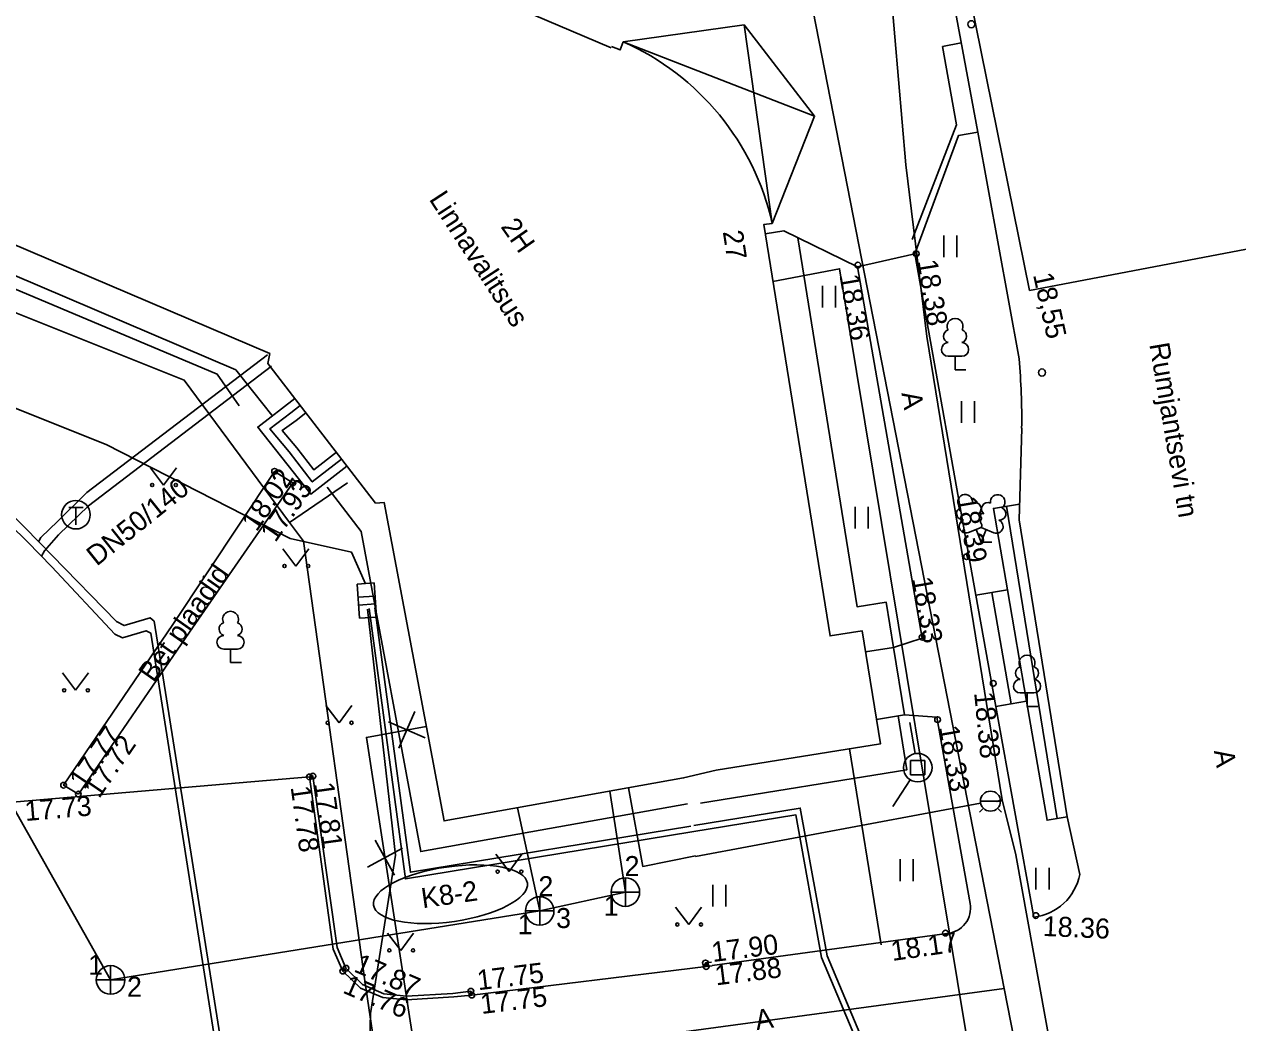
# Model space of a CAD drawing. Extents: x 713497 to 713863, y 6590062 to 6590327.
# Drawn here: x 713604.95 to 713647.37, y 6590159.98 to 6590194.89 of the extents above; entities that cross this region are included whole.
import ezdxf

# ---------------------------------------------------------------- set-up
doc = ezdxf.new("R2010")
doc.units = 0
for name, color, linetype in [('AED', 7, 'Continuous'), ('DKAEV', 7, 'Continuous'), ('HALJASTUS', 7, 'Continuous'), ('HOONE', 7, 'Continuous'), ('HOONEDET', 7, 'Continuous'), ('KAEVU_NR', 7, 'Continuous'), ('KKAEV', 7, 'Continuous'), ('KORGUS', 7, 'Continuous'), ('KTRASS', 7, 'Continuous'), ('MPKAABEL', 7, 'Continuous'), ('POST', 7, 'Continuous'), ('PUU', 7, 'Continuous'), ('SITRASS', 7, 'Continuous'), ('TEE', 7, 'Continuous'), ('TKAEV', 7, 'Continuous'), ('TORU NR', 7, 'Continuous'), ('TTRASS', 7, 'Continuous'), ('VKAEV', 7, 'Continuous'), ('VTRASS', 7, 'Continuous'), ('Слой 1', 7, 'Continuous')]:
    doc.layers.add(name, color=color, linetype=linetype)

msp = doc.modelspace()

# ---------------------------------------------------------------- linework, layer by layer
at = {"layer": 'AED'}
msp.add_lwpolyline([(713634.907, 6590162.705), (713633.803, 6590169.554)], dxfattribs=at)
at = {"layer": 'DKAEV'}
for p, q in [((713635.937, 6590168.645), (713635.937, 6590169.145)), ((713635.937, 6590169.145), (713636.437, 6590169.145)), ((713636.437, 6590169.145), (713636.437, 6590168.645)), ((713636.437, 6590168.645), (713635.937, 6590168.645))]:
    msp.add_line(p, q, dxfattribs=at)
msp.add_circle((713636.187, 6590168.895), 0.5, dxfattribs=at)
at = {"layer": 'HALJASTUS'}
for p, q in [((713637.102, 6590187.505), (713637.102, 6590186.744)), ((713637.558, 6590187.505), (713637.558, 6590186.744)), ((713632.856, 6590185.741), (713632.856, 6590184.98)), ((713633.311, 6590185.741), (713633.311, 6590184.98)), ((713637.718, 6590181.712), (713637.718, 6590180.951)), ((713638.173, 6590181.712), (713638.173, 6590180.951)), ((713609.359, 6590179.383), (713609.823, 6590178.776)), ((713609.823, 6590178.776), (713610.268, 6590179.383)), ((713633.997, 6590178.013), (713633.997, 6590177.252)), ((713634.453, 6590178.013), (713634.453, 6590177.252)), ((713613.986, 6590176.551), (713614.449, 6590175.944)), ((713614.449, 6590175.944), (713614.895, 6590176.551)), ((713606.283, 6590172.207), (713606.747, 6590171.6)), ((713606.747, 6590171.6), (713607.192, 6590172.207)), ((713615.499, 6590171.071), (713615.962, 6590170.464)), ((713615.962, 6590170.464), (713616.408, 6590171.071)), ((713621.437, 6590165.866), (713621.901, 6590165.259)), ((713621.901, 6590165.259), (713622.346, 6590165.866)), ((713635.571, 6590165.691), (713635.571, 6590164.93)), ((713636.026, 6590165.691), (713636.026, 6590164.93)), ((713640.321, 6590165.392), (713640.321, 6590164.631)), ((713640.776, 6590165.392), (713640.776, 6590164.631)), ((713629.028, 6590164.801), (713629.028, 6590164.04)), ((713629.483, 6590164.801), (713629.483, 6590164.04)), ((713627.72, 6590164.016), (713628.183, 6590163.41)), ((713628.183, 6590163.41), (713628.629, 6590164.016)), ((713617.65, 6590163.113), (713618.114, 6590162.506)), ((713618.114, 6590162.506), (713618.559, 6590163.113))]:
    msp.add_line(p, q, dxfattribs=at)
msp.add_lwpolyline([(713634.083, 6590186.407), (713636.085, 6590186.861)], dxfattribs=at)
for centre in [(713609.422, 6590178.776), (713610.251, 6590178.776), (713614.048, 6590175.944), (713614.877, 6590175.944), (713606.346, 6590171.6), (713607.174, 6590171.6), (713615.561, 6590170.464), (713616.39, 6590170.464), (713621.5, 6590165.259), (713622.328, 6590165.259), (713627.782, 6590163.41), (713628.611, 6590163.41), (713617.713, 6590162.506), (713618.541, 6590162.506)]:
    msp.add_circle(centre, 0.055, dxfattribs=at)
at = {"layer": 'HOONE'}
for points in [[(713591.105, 6590192.933), (713597.112, 6590207.263), (713600.77, 6590205.702), (713600.388, 6590204.728), (713625.464, 6590194.063)], [(713625.893, 6590194.273), (713630.115, 6590194.87), (713632.579, 6590191.676), (713631.097, 6590187.925)], [(713631.097, 6590187.925), (713630.801, 6590187.883), (713633.12, 6590173.501), (713634.243, 6590173.682), (713634.881, 6590169.727), (713629.138, 6590168.802), (713628.003, 6590168.533), (713619.626, 6590167.035), (713617.534, 6590178.165), (713617.232, 6590178.145), (713613.469, 6590183.026), (713613.531, 6590183.375), (713591.105, 6590192.933)], [(713616.233, 6590179.441), (713614.964, 6590178.463), (713613.113, 6590180.801), (713614.412, 6590181.803)], [(713634.362, 6590172.944), (713635.342, 6590173.102), (713635.722, 6590170.742), (713634.743, 6590170.584)], [(713636.1, 6590169.387), (713635.909, 6590170.468)], [(713635.917, 6590168.474), (713635.311, 6590167.533)]]:
    msp.add_lwpolyline(points, dxfattribs=at)
msp.add_arc((713622.223, 6590185.958), 9.09, 12.4976, 66.1826, dxfattribs=at)
at = {"layer": 'HOONEDET'}
for p, q in [((713631.097, 6590187.925), (713630.115, 6590194.87)), ((713632.579, 6590191.676), (713625.893, 6590194.273))]:
    msp.add_line(p, q, dxfattribs=at)
for points in [[(713596.129, 6590207.599), (713589.787, 6590192.438), (713612.343, 6590182.807), (713613.607, 6590181.216)], [(713625.478, 6590194.115), (713625.783, 6590193.994), (713625.893, 6590194.273)], [(713631.097, 6590187.925), (713630.801, 6590187.883), (713633.12, 6590173.501), (713634.243, 6590173.682), (713634.881, 6590169.727), (713629.138, 6590168.802)], [(713616.047, 6590179.682), (713615.016, 6590178.887), (713614.208, 6590179.934), (713613.54, 6590180.746), (713614.273, 6590181.306), (713614.6, 6590181.558)], [(713614.798, 6590181.303), (713614.453, 6590181.037), (713613.97, 6590180.689), (713614.483, 6590180.076), (713615.071, 6590179.314), (713615.861, 6590179.923)], [(713615.541, 6590178.701), (713616.733, 6590177.153), (713618.814, 6590165.958), (713628.14, 6590167.631)]]:
    msp.add_lwpolyline(points, dxfattribs=at)
msp.add_arc((713622.223, 6590185.958), 9.09, 12.4976, 66.1826, dxfattribs=at)
at = {"layer": 'KAEVU_NR'}
msp.add_ellipse((713619.851, 6590164.47), major_axis=(2.689, 0.388), ratio=0.353371, dxfattribs=at)
at = {"layer": 'KKAEV'}
for p, q in [((713625.965, 6590164.044), (713625.965, 6590165.044)), ((713625.465, 6590164.544), (713626.465, 6590164.544)), ((713622.97, 6590163.383), (713622.97, 6590164.383)), ((713622.47, 6590163.883), (713623.47, 6590163.883)), ((713607.97, 6590160.971), (713607.97, 6590161.971)), ((713607.47, 6590161.471), (713608.47, 6590161.471))]:
    msp.add_line(p, q, dxfattribs=at)
for centre in [(713625.965, 6590164.544), (713622.97, 6590163.883), (713607.97, 6590161.471)]:
    msp.add_circle(centre, 0.5, dxfattribs=at)
at = {"layer": 'KORGUS'}
for centre, radius in [((713638.06, 6590194.89), 0.125), ((713636.132, 6590186.867), 0.1), ((713634.096, 6590186.469), 0.1), ((713640.53, 6590182.71), 0.125), ((713613.702, 6590179.256), 0.1), ((713614.341, 6590178.855), 0.1), ((713637.893, 6590176.272), 0.1), ((713636.338, 6590173.454), 0.1), ((713638.828, 6590171.843), 0.1), ((713636.882, 6590170.572), 0.1), ((713606.327, 6590168.281), 0.1), ((713614.919, 6590168.57), 0.1), ((713615.041, 6590168.601), 0.1), ((713606.842, 6590167.969), 0.1), ((713640.319, 6590163.721), 0.1), ((713637.157, 6590163.111), 0.1), ((713616.198, 6590161.88), 0.1), ((713628.763, 6590162.064), 0.1), ((713628.791, 6590161.942), 0.1), ((713616.087, 6590161.78), 0.1), ((713620.564, 6590161.078), 0.1), ((713620.595, 6590160.942), 0.1)]:
    msp.add_circle(centre, radius, dxfattribs=at)
at = {"layer": 'KTRASS'}
for points in [[(713607.97, 6590161.471), (713597.64, 6590179.782)], [(713625.965, 6590164.544), (713625.424, 6590168.071)], [(713622.97, 6590163.883), (713622.198, 6590167.495)], [(713625.965, 6590164.544), (713622.97, 6590163.883)], [(713622.97, 6590163.883), (713607.97, 6590161.471)]]:
    msp.add_lwpolyline(points, dxfattribs=at)
at = {"layer": 'MPKAABEL'}
for points in [[(713649.332, 6590187.338), (713640.094, 6590185.585), (713635.77, 6590206.95), (713632.04, 6590224.25), (713630.57, 6590226.81), (713628.65, 6590228.67), (713627.42, 6590229.49), (713598.73, 6590243.21), (713583.058, 6590248.245), (713565.046, 6590256.189), (713523.612, 6590274.149), (713521.905, 6590274.877)], [(713616.886, 6590175.327), (713616.393, 6590176.426), (713614.251, 6590176.909), (713607.81, 6590180.2), (713588.598, 6590187.876), (713587.389, 6590189.739), (713589.126, 6590193.776), (713594.035, 6590205.549), (713591.42, 6590211.04), (713578.93, 6590215.939), (713578.375, 6590215.066)], [(713593.578, 6590189.232), (713594.274, 6590188.953), (713610.545, 6590182.449), (713614.229, 6590177.468)], [(713616.25, 6590178.85), (713614.229, 6590177.468)], [(713614.229, 6590177.468), (713614.715, 6590176.812), (713616.87, 6590161.36), (713618.55, 6590150.08)], [(713623.164, 6590135.391), (713619.07, 6590137.22), (713617.908, 6590148.88), (713616.96, 6590156.73), (713617.053, 6590160.295), (713617.928, 6590165.834), (713616.95, 6590174.44)], [(713628.288, 6590166.652), (713618.278, 6590165.005), (713617.01, 6590174.458)], [(713628.258, 6590166.852), (713618.45, 6590165.24), (713617.209, 6590174.485)], [(713628.364, 6590166.869), (713632.08, 6590167.48), (713633.015, 6590162.313), (713634.41, 6590159.02), (713637.59, 6590156.404), (713640.542, 6590143.998), (713655.527, 6590146.824), (713666.053, 6590148.923), (713666.104, 6590148.937), (713666.053, 6590148.923), (713676.52, 6590152.11), (713677.82, 6590153.38), (713679.31, 6590155.11), (713679.81, 6590159.44), (713679.75, 6590161.04), (713679.53, 6590162.08), (713679.1, 6590163.05), (713677.79, 6590165.07), (713675.3, 6590167.39), (713673.09, 6590169.87), (713671.63, 6590170.7), (713670.72, 6590170.92), (713670.037, 6590170.92)], [(713712.95, 6590130.05), (713709.16, 6590129.42), (713701.69, 6590129.47), (713690.5, 6590129.51), (713688.19, 6590129.12), (713683.66, 6590141.1), (713679.81, 6590148.4), (713679.37, 6590149.39), (713679.04, 6590150.26), (713678.83, 6590150.79), (713678.48, 6590151.44), (713677.98, 6590152.02), (713677.43, 6590152.31), (713676.95, 6590152.28), (713676.524, 6590152.014), (713670.183, 6590149.934), (713666.077, 6590148.723), (713655.565, 6590146.628), (713640.392, 6590143.766), (713637.411, 6590156.292), (713634.246, 6590158.892), (713632.822, 6590162.256), (713631.92, 6590167.25), (713628.288, 6590166.652)]]:
    msp.add_lwpolyline(points, dxfattribs=at)
at = {"layer": 'POST'}
for p, q in [((713617.18, 6590175.354), (713616.584, 6590175.314)), ((713616.584, 6590175.314), (713616.665, 6590174.122)), ((713617.261, 6590174.162), (713617.18, 6590175.354)), ((713617.211, 6590174.894), (713616.616, 6590174.853)), ((713617.229, 6590174.623), (713616.634, 6590174.582)), ((713616.665, 6590174.122), (713617.261, 6590174.162))]:
    msp.add_line(p, q, dxfattribs=at)
at = {"layer": 'PUU'}
for p, q in [((713637.732, 6590183.281), (713637.252, 6590183.281)), ((713637.492, 6590182.806), (713637.492, 6590183.281)), ((713637.872, 6590182.806), (713637.492, 6590182.806)), ((713637.96, 6590177.115), (713638.405, 6590177.29)), ((713638.4, 6590176.78), (713638.225, 6590177.22)), ((713638.4, 6590176.78), (713638.58, 6590177.22)), ((713638.405, 6590177.29), (713638.845, 6590177.11)), ((713638.78, 6590176.78), (713638.4, 6590176.78)), ((713612.403, 6590173.041), (713611.923, 6590173.041)), ((713612.163, 6590172.566), (713612.163, 6590173.041)), ((713612.543, 6590172.566), (713612.163, 6590172.566)), ((713640.248, 6590171.507), (713639.768, 6590171.507)), ((713640.008, 6590171.032), (713640.008, 6590171.507)), ((713640.388, 6590171.032), (713640.008, 6590171.032))]:
    msp.add_line(p, q, dxfattribs=at)
msp.add_lwpolyline([(713638.405, 6590177.785), (713638.385, 6590177.71), (713638.385, 6590177.69), (713638.395, 6590177.66), (713638.415, 6590177.625), (713638.42, 6590177.605), (713638.405, 6590177.57), (713638.38, 6590177.52), (713638.375, 6590177.495), (713638.38, 6590177.48), (713638.39, 6590177.45), (713638.425, 6590177.39), (713638.43, 6590177.37), (713638.425, 6590177.35), (713638.41, 6590177.315), (713638.405, 6590177.29)], dxfattribs=at)
for centre, radius, start, end in [((713637.492, 6590184.326), 0.277, 332.5799, 207.4201), ((713637.321, 6590183.979), 0.233, 109.0217, 253.1415), ((713637.662, 6590183.979), 0.233, 286.8508, 70.9859), ((713637.254, 6590183.519), 0.238, 90.0016, 269.3953), ((713637.729, 6590183.519), 0.238, 270.6047, 89.9984), ((713637.843, 6590178.194), 0.256, 111.5027, 232.5173), ((713637.843, 6590178.194), 0.256, 350.4856, 111.5002), ((713638.178, 6590177.944), 0.224, 308.5041, 111.5725), ((713638.641, 6590177.939), 0.225, 67.7016, 230.5126), ((713638.979, 6590178.185), 0.256, 67.6168, 188.6314), ((713638.979, 6590178.185), 0.256, 306.5997, 67.6143), ((713637.769, 6590177.783), 0.224, 111.4304, 274.4987), ((713638.404, 6590177.547), 0.237, 66.7655, 111.5015), ((713639.046, 6590177.773), 0.224, 264.6183, 67.6866), ((713637.874, 6590177.338), 0.237, 111.5014, 291.5004), ((713638.935, 6590177.33), 0.237, 247.6166, 67.6155), ((713612.163, 6590174.086), 0.277, 332.5799, 207.4201), ((713611.993, 6590173.739), 0.233, 109.0217, 253.1415), ((713612.333, 6590173.739), 0.233, 286.8508, 70.9859), ((713611.926, 6590173.278), 0.238, 90.0016, 269.3953), ((713612.4, 6590173.278), 0.238, 270.6047, 89.9984), ((713640.008, 6590172.552), 0.277, 332.5799, 207.4201), ((713639.838, 6590172.204), 0.233, 109.0217, 253.1415), ((713640.178, 6590172.204), 0.233, 286.8508, 70.9859), ((713639.771, 6590171.744), 0.238, 90.0016, 269.3953), ((713640.246, 6590171.744), 0.238, 270.6047, 89.9984)]:
    msp.add_arc(centre, radius, start, end, dxfattribs=at)
at = {"layer": 'SITRASS'}
for p, q in [((713618.61, 6590170.855), (713618.051, 6590169.571)), ((713617.689, 6590170.493), (713618.972, 6590169.933)), ((713617.896, 6590165.134), (713617.223, 6590166.361)), ((713616.946, 6590165.411), (713618.174, 6590166.084))]:
    msp.add_line(p, q, dxfattribs=at)
for points in [[(713612.46, 6590181.55), (713611.7, 6590182.65), (713603.47, 6590186.11), (713602.51, 6590186.66), (713589.634, 6590191.941), (713560.96, 6590203.19), (713554.11, 6590205.87)], [(713631.121, 6590185.897), (713633.455, 6590186.339), (713638.75, 6590154.309), (713660.08, 6590156.42), (713665.095, 6590157.143)], [(713619.005, 6590170.338), (713616.91, 6590169.95), (713619.12, 6590155.66), (713619.72, 6590151.16), (713619.81, 6590145.36), (713621.97, 6590134.21), (713623.094, 6590127.673)]]:
    msp.add_lwpolyline(points, dxfattribs=at)
at = {"layer": 'TEE'}
for p, q in [((713641.06, 6590167.117), (713639.289, 6590178.035)), ((713639.323, 6590175.115), (713639.993, 6590171.216)), ((713638.773, 6590175.021), (713639.457, 6590171.124))]:
    msp.add_line(p, q, dxfattribs=at)
for points in [[(713639.728, 6590183.194), (713638.283, 6590191.119), (713637.539, 6590195.136), (713632.966, 6590219.69)], [(713637.056, 6590194.116), (713637.705, 6590194.237)], [(713637.056, 6590194.116), (713637.542, 6590191.371), (713635.988, 6590187.363)], [(713638.283, 6590191.119), (713637.608, 6590190.999), (713636.085, 6590186.861)], [(713634.083, 6590186.407), (713631.501, 6590187.664), (713630.853, 6590187.559)], [(713635.342, 6590173.102), (713635.087, 6590174.681), (713634.072, 6590174.517), (713631.991, 6590187.425)], [(713638.223, 6590174.926), (713636.085, 6590186.861)], [(713634.083, 6590186.407), (713636.343, 6590173.423), (713635.342, 6590173.102)], [(713641.852, 6590165.162), (713641.412, 6590167.177), (713639.729, 6590177.556), (713639.82, 6590180.769)], [(713606.842, 6590167.969), (713606.327, 6590168.281), (713610.14, 6590173.9), (713613.702, 6590179.256), (713614.341, 6590178.855), (713610.726, 6590173.632), (713606.842, 6590167.969)], [(713638.223, 6590174.926), (713639.323, 6590175.115), (713638.835, 6590177.961), (713639.744, 6590178.109)], [(713638.921, 6590171.032), (713638.223, 6590174.926)], [(713641.412, 6590167.177), (713640.707, 6590167.056), (713639.993, 6590171.216), (713638.921, 6590171.032)], [(713640.241, 6590163.667), (713638.921, 6590171.032)], [(713628.593, 6590167.656), (713635.807, 6590168.819), (713635.503, 6590170.707)], [(713635.722, 6590170.742), (713636.86, 6590170.656), (713638.019, 6590164.15)], [(713586.796, 6590159.531), (713586.786, 6590166.591), (713598.149, 6590167.277), (713604.677, 6590167.703), (713614.919, 6590168.57)], [(713614.919, 6590168.57), (713615.041, 6590168.601), (713615.885, 6590162.611), (713616.198, 6590161.88), (713616.776, 6590161.309), (713617.517, 6590160.991), (713618.311, 6590160.909), (713619.929, 6590160.992), (713620.564, 6590161.078), (713620.595, 6590160.942)], [(713614.919, 6590168.57), (713615.753, 6590162.543), (713616.087, 6590161.78), (713616.703, 6590161.18), (713617.489, 6590160.861), (713618.314, 6590160.773), (713619.968, 6590160.883), (713620.595, 6590160.942), (713628.791, 6590161.942), (713629.001, 6590161.968)], [(713637.204, 6590163.094), (713628.999, 6590161.976)], [(713628.791, 6590161.942), (713628.763, 6590162.064), (713628.982, 6590162.091)]]:
    msp.add_lwpolyline(points, dxfattribs=at)
for centre, radius, start, end in [((713616.187, 6590181.086), 23.635, 359.2292, 5.1156), ((713640.027, 6590165.514), 1.859, 276.6338, 349.0753), ((713637.133, 6590163.992), 0.9, 274.5297, 10.0984)]:
    msp.add_arc(centre, radius, start, end, dxfattribs=at)
at = {"layer": 'TKAEV'}
for p, q in [((713606.508, 6590177.99), (713607.008, 6590177.99)), ((713606.758, 6590177.39), (713606.758, 6590177.99))]:
    msp.add_line(p, q, dxfattribs=at)
msp.add_circle((713606.758, 6590177.74), 0.5, dxfattribs=at)
at = {"layer": 'TTRASS'}
for points in [[(713567.466, 6590198.63), (713578.401, 6590193.782), (713589.512, 6590189.073), (713600.569, 6590184.368), (713601.451, 6590183.992), (713601.524, 6590183.896), (713601.155, 6590183.08), (713600.626, 6590181.777), (713600.676, 6590181.533), (713602.872, 6590179.376), (713604.978, 6590177.28), (713605.925, 6590176.311), (713608.173, 6590174), (713608.441, 6590173.865), (713609.351, 6590174.136), (713609.498, 6590174.017), (713612.504, 6590155.073), (713613.075, 6590150.266), (713615.084, 6590138.478)], [(713567.885, 6590198.124), (713578.819, 6590193.334), (713589.871, 6590188.505), (713601.021, 6590183.871), (713601.066, 6590183.741), (713600.225, 6590181.685), (713600.269, 6590181.473), (713605.066, 6590176.79), (713605.92, 6590175.914), (713608.121, 6590173.566), (713608.385, 6590173.433), (713609.208, 6590173.681), (713609.37, 6590173.599), (713612.302, 6590155.005), (713612.943, 6590150.015), (713614.851, 6590138.172)], [(713605.451, 6590176.796), (713605.534, 6590176.947), (713606.124, 6590177.512), (713607.142, 6590178.52), (713613.457, 6590183.334)], [(713605.556, 6590176.287), (713605.661, 6590176.473), (713606.145, 6590177.041), (713607.191, 6590178.049), (713613.597, 6590182.932)]]:
    msp.add_lwpolyline(points, dxfattribs=at)
at = {"layer": 'VKAEV'}
for p, q in [((713638.482, 6590167.476), (713638.342, 6590167.336)), ((713638.379, 6590167.723), (713639.079, 6590167.723)), ((713638.976, 6590167.476), (713639.116, 6590167.336))]:
    msp.add_line(p, q, dxfattribs=at)
msp.add_circle((713638.729, 6590167.723), 0.35, dxfattribs=at)
at = {"layer": 'VTRASS'}
for points in [[(713656.584, 6590071.475), (713656.374, 6590072.423), (713654.566, 6590083.572), (713651.757, 6590099.218), (713649.481, 6590111.002), (713648.142, 6590117.611), (713647.31, 6590122.509), (713646.414, 6590125.725), (713646.252, 6590126.242), (713646.237, 6590126.353), (713646.208, 6590126.464), (713646.178, 6590126.898), (713644.112, 6590140.998), (713641.664, 6590154.51), (713639.62, 6590165.841), (713639.136, 6590167.772), (713636.504, 6590183.972), (713635.775, 6590189.972), (713635.261, 6590195.956), (713632.54, 6590225.141)], [(713626.079, 6590168.189), (713626.571, 6590165.443), (713628.417, 6590165.81)], [(713628.42, 6590165.789), (713638.385, 6590167.658)], [(713639.136, 6590167.772), (713638.95, 6590167.715), (713638.729, 6590167.723)]]:
    msp.add_lwpolyline(points, dxfattribs=at)
at = {"layer": 'Слой 1'}
for points in [[(713639.21, 6590161.17), (713619.31, 6590158.48), (713605.01, 6590158.14), (713587.01, 6590157.64), (713579.15, 6590161.09), (713575.14, 6590170.32), (713594.16, 6590210.61), (713559.07, 6590225.5), (713569.4, 6590249.89), (713586.61, 6590242.91), (713588.04, 6590239.97), (713627.31, 6590223.7), (713629.09, 6590219.58), (713632.13, 6590197.39)], [(713605.01, 6590158.14), (713619.31, 6590158.48), (713639.21, 6590161.17), (713646.6, 6590123.47), (713610.16, 6590116.83)]]:
    msp.add_lwpolyline(points, close=True, dxfattribs=at)

# ---------------------------------------------------------------- texts
at = {"layer": 'HOONE'}
for s, rotation, p in [('Linnavalitsus', 303.0768, (713619.084, 6590188.771)), ('2H', 305.1053, (713621.589, 6590187.808)), ('27', 278.8349, (713629.369, 6590187.637))]:
    msp.add_text(s, height=0.7, rotation=rotation, dxfattribs=at).set_placement(p)
at = {"layer": 'KAEVU_NR'}
msp.add_text('K8-2', height=0.7, rotation=8.2075, dxfattribs=at).set_placement((713618.881, 6590163.977))
at = {"layer": 'KORGUS'}
for s, rotation, p in [(' 18.38', 279.1309, (713636.132, 6590186.867)), ('18,55', 282.3666, (713640.215, 6590186.13)), (' 18.36', 279.774, (713633.406, 6590186.35)), (' 18.02', 55.3117, (713612.923, 6590176.901)), (' 17.93', 55.3117, (713613.582, 6590176.529)), (' 18.39', 279.547, (713637.504, 6590178.584)), (' 18.33', 279.774, (713635.94, 6590175.765)), (' 18.38', 275.5948, (713638.131, 6590171.775)), (' 17.77', 55.5555, (713606.904, 6590167.885)), (' 17.72', 55.5555, (713607.419, 6590167.573)), (' 18.33', 279.7948, (713636.882, 6590170.572)), (' 17.81', 277.8784, (713615.041, 6590168.601)), (' 17.73', 4.8386, (713604.736, 6590167.005)), (' 17.78', 277.8784, (713614.226, 6590168.474)), (' 18.36', 357.5482, (713640.289, 6590163.022)), (' 17.90', 7.1536, (713628.763, 6590162.064)), (' 18.17', 8.2935, (713635.042, 6590162.095)), (' 17.87', 336.7734, (713616.198, 6590161.88)), (' 17.75', 6.9563, (713620.564, 6590161.078)), (' 17.88', 7.1536, (713628.878, 6590161.247)), (' 17.76', 336.7734, (713615.811, 6590161.137)), (' 17.75', 6.9563, (713620.68, 6590160.247))]:
    msp.add_text(s, height=0.7, rotation=rotation, dxfattribs=at).set_placement(p)
at = {"layer": 'TEE'}
for s, rotation, p in [('Rumjantsevi tn', 279.6715, (713644.28, 6590183.7)), ('A', 279.6645, (713635.613, 6590181.992)), ('Bet plaadid', 54.9336, (713609.467, 6590171.846)), ('A', 279.3399, (713646.539, 6590169.482)), ('A', 9.1345, (713630.559, 6590159.714))]:
    msp.add_text(s, height=0.7, rotation=rotation, dxfattribs=at).set_placement(p)
at = {"layer": 'TORU NR'}
for s, p in [('2', (713625.939, 6590165.103)), ('2', (713622.925, 6590164.4)), ('1', (713625.21, 6590163.715)), ('1', (713622.201, 6590163.072)), ('3', (713623.544, 6590163.286)), ('1', (713607.185, 6590161.651)), ('2', (713608.542, 6590160.885))]:
    msp.add_text(s, height=0.7, dxfattribs=at).set_placement(p)
at = {"layer": 'TTRASS'}
msp.add_text('DN50/140', height=0.7, rotation=38.6231, dxfattribs=at).set_placement((713607.483, 6590175.919))

doc.saveas('drawing.dxf')
